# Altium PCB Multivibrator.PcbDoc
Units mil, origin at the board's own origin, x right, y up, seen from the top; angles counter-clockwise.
Board outline 2000 x 2000 mil, 2 copper layers (Top Layer, Bottom Layer); 9 components, 6 nets, 20 pads, 0 vias.
Unrouted connection lines stored in the file: 14.
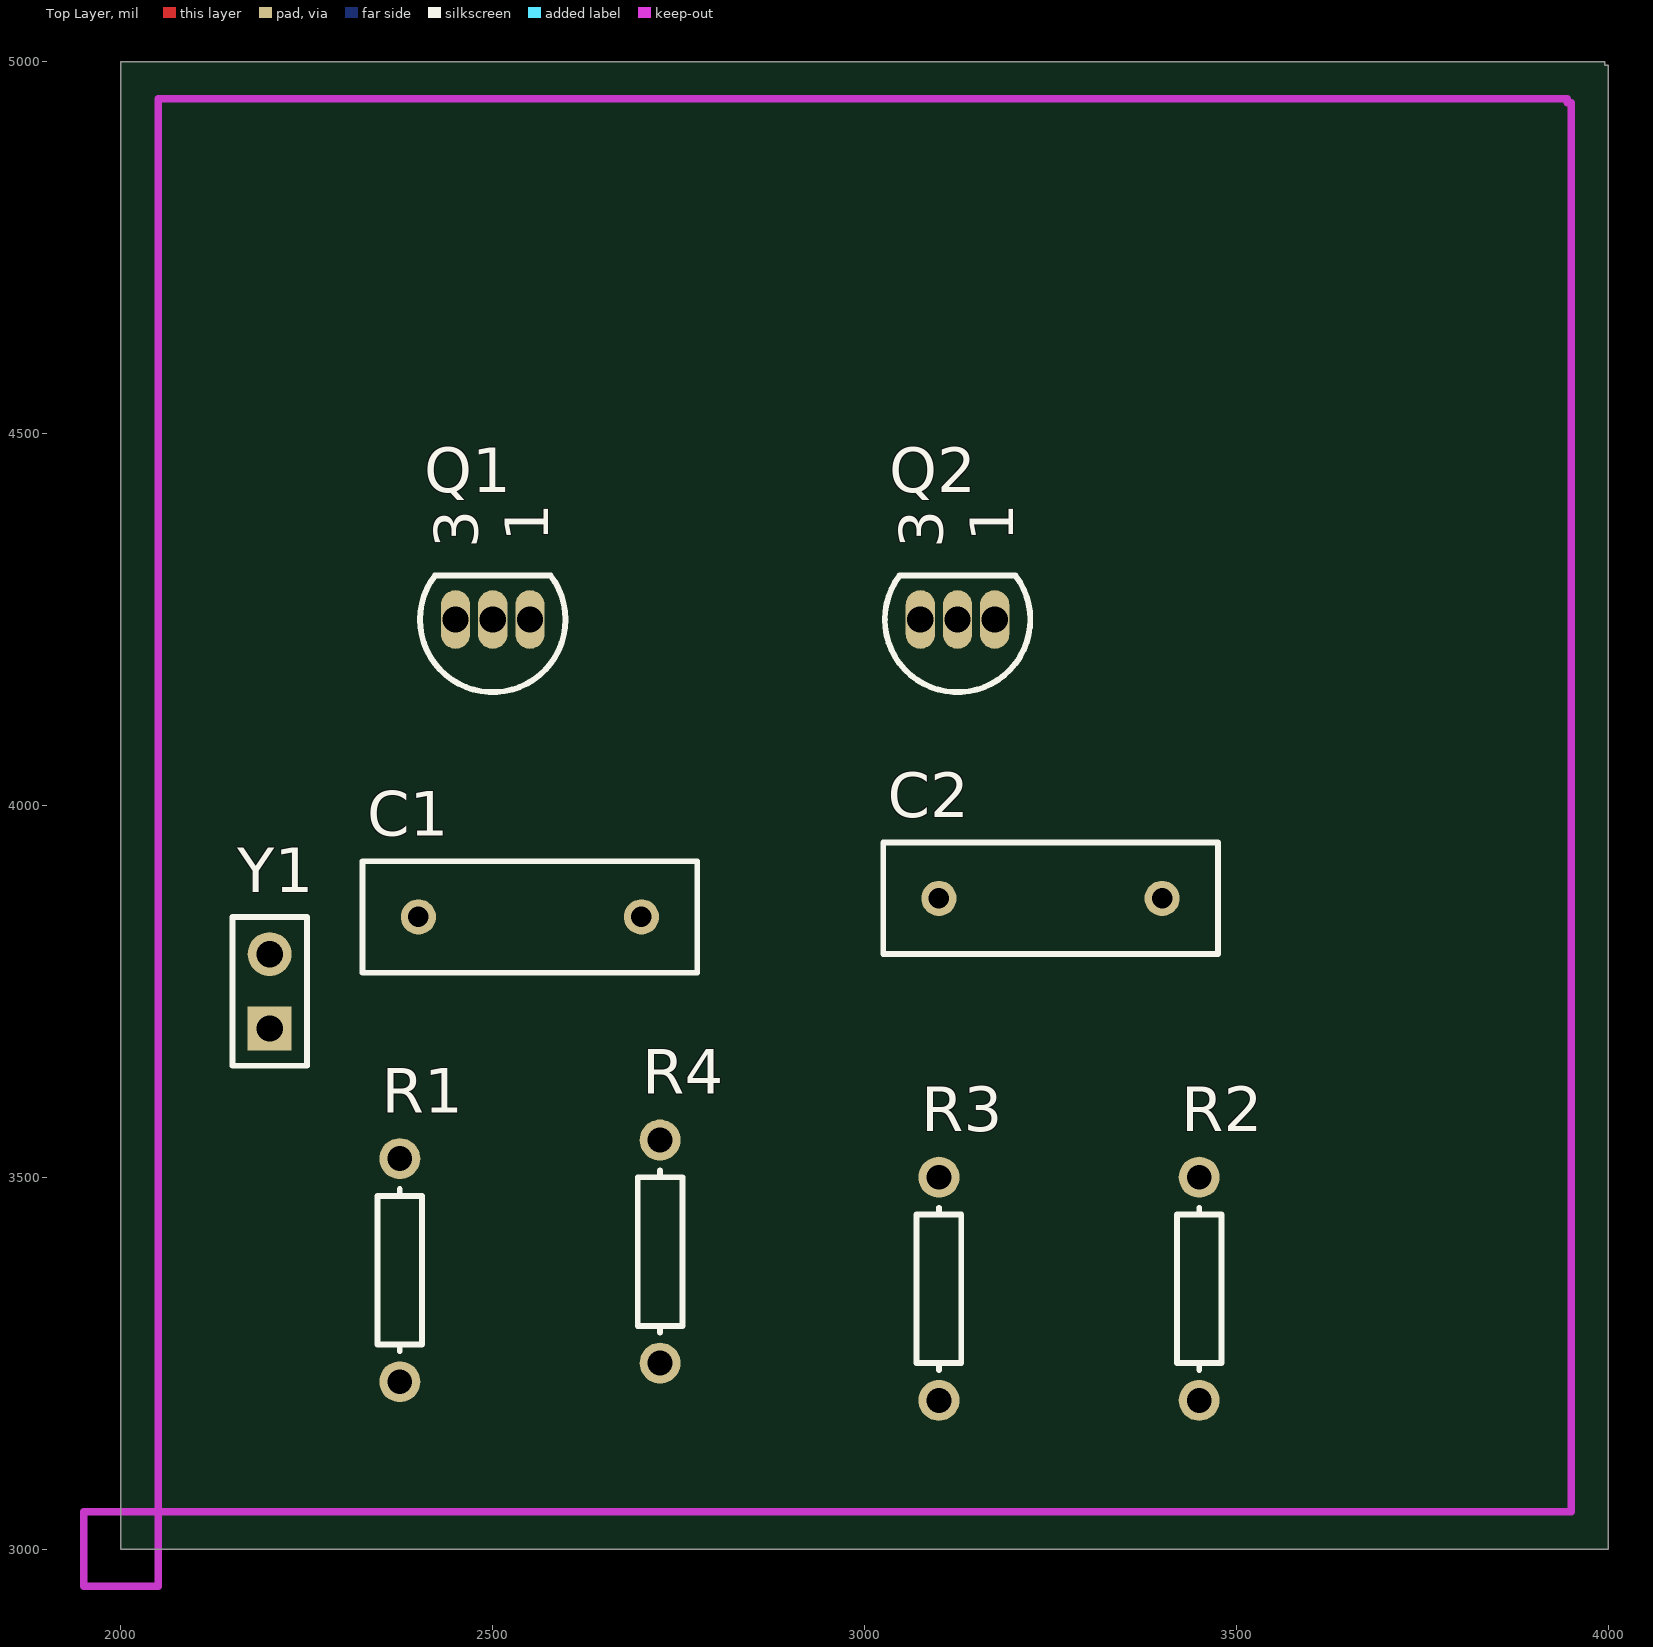
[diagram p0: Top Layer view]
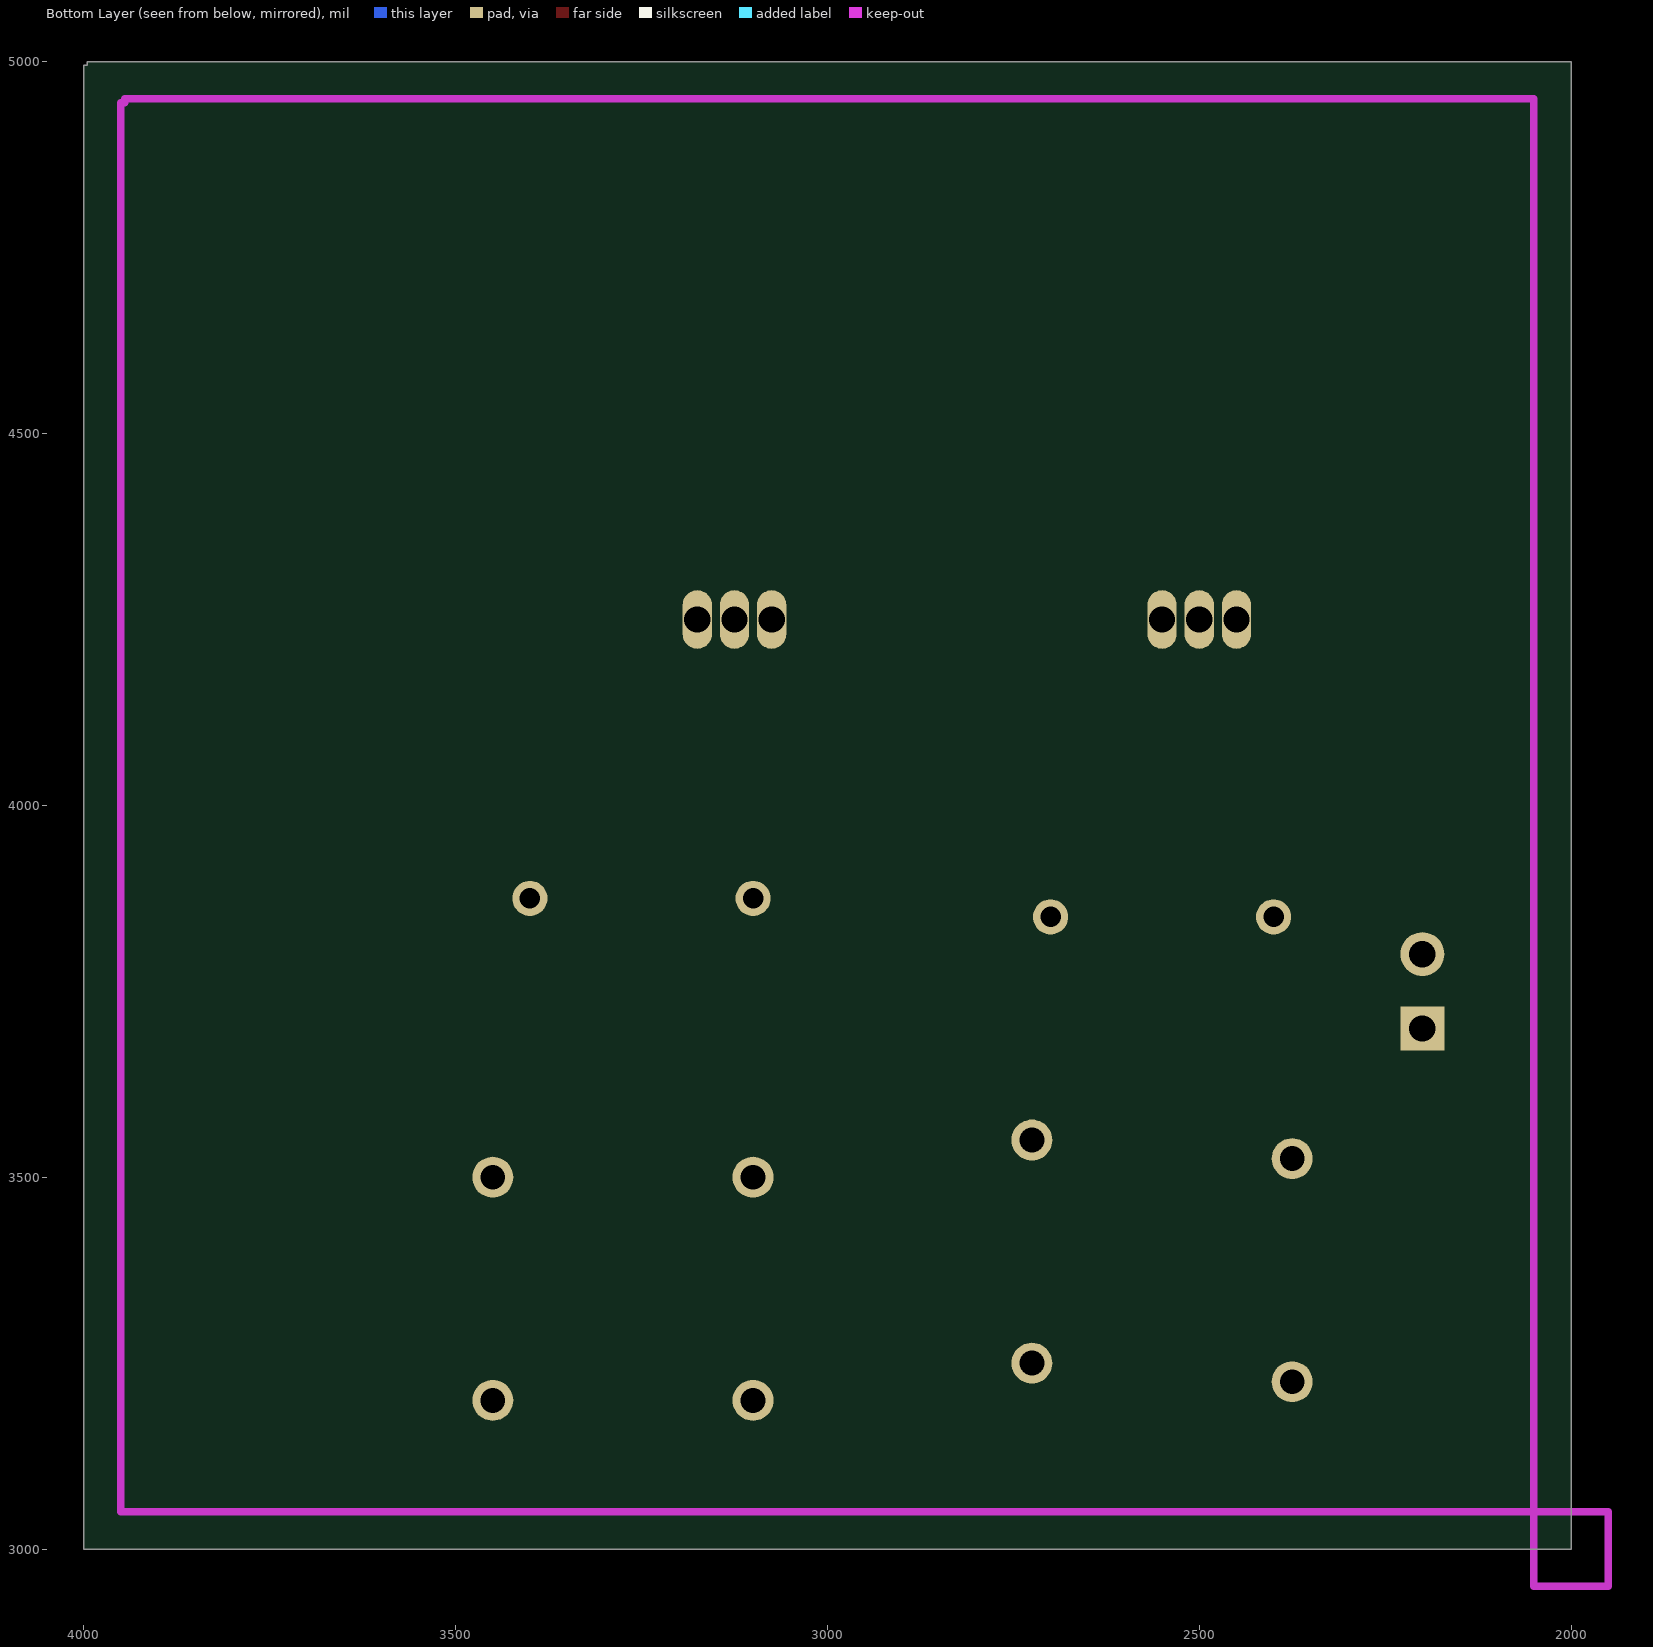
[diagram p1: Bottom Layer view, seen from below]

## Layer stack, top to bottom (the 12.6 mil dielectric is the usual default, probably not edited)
Top Layer: signal copper 1.4
Dielectric: core 12.6, FR-4, Dk 4.8
Bottom Layer: signal copper 1.4

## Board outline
2000,3000 4000,3000 4000,4995 3995,4995 3995,5000 2000,5000

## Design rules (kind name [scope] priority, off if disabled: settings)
Clearance [All] p1: gap=13
PolygonConnect [All] p1: connectstyle=Relief reliefconductorwidth=10 reliefentries=4 polygonreliefangle="90 Angle"
RoutingVias [All] p1: holewidth=32 width=62 viastyle="Through Hole" minholewidth=28 minwidth=50 maxholewidth=28 maxwidth=50
SilkscreenOverComponentPads [All] p1: minsilkscreentomaskgap=10
SolderMaskExpansion [All] p1: expansion=4
Width 12V [(InNet('12V') OR InNet('GND'))] p1: maxlimit=25 minlimit=25 preferedwidth=25
Width [All] p2: maxlimit=12 minlimit=12 preferedwidth=12
27 further rules are at their usual default settings.

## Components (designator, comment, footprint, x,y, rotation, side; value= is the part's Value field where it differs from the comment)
C1 "20n" RAD-0.3 2550,3850 r0 top
C2 "20n" RAD-0.3 3250,3875 r0 top
Q1 "2N3904" BCY-W3/E4 2500,4250 r90 top
Q2 "2N3904" BCY-W3/E4 3125,4250 r90 top
R1 "100k" AXIAL-0.3 2375,3375 r270 top
R2 "100k" AXIAL-0.3 3450,3350 r270 top
R3 "1k" AXIAL-0.3 3100,3350 r270 top
R4 "1k" AXIAL-0.3 2725,3400 r270 top
Y1 "Header 2" HDR1X2 2200,3700 r90 top

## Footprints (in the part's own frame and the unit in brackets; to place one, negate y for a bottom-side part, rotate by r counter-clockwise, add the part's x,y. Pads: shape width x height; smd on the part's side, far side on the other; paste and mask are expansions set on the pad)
AXIAL-0.3 [mm] "Axial Device, Thru-Hole; 2 Leads; 0.3 in Pin Spacing"
  round 1.4 hole 0.85: 1(-3.81,0) 2(3.81,0)
  silkscreen extent -2.77,-0.76 2.77,0.76
BCY-W3/E4 [mm] "TO, Flat Index; 3 In-Line, Axial Leads; Body Dia. 4.5mm; Leads 0.51 x 0.48 mm (max)"
  oval 2x1 hole 0.9: 1(0,-1.27) 2(0,0) 3(0,1.27)
  silkscreen extent -2.48,-2.48 1.5,2.48
HDR1X2 [mm] "Connector; Header; 2 Position"
  rect 1.5x1.5 hole 0.9: 1(0,0)
  round 1.5 hole 0.9: 2(2.54,0)
  silkscreen extent -1.27,-1.27 3.81,1.27
RAD-0.3 [mm] "Radial Cap, Thru-Hole; 2 Leads; 0.3 in Pin Spacing"
  round 1.2 hole 0.7: 1(-3.81,0) 2(3.81,0)
  silkscreen extent -5.71,-1.91 5.71,1.91

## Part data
C1 C2: library part Cap, "Capacitor"
Q1 Q2: "NPN General Purpose Amplifier"
R1 R2 R3 R4: library part Res1, "Resistor"
Y1: "Header, 2-Pin"

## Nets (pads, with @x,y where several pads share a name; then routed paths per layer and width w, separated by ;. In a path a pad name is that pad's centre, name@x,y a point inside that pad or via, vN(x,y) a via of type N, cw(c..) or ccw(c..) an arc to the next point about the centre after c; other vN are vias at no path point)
12V: R1.2 R2.2 R3.2 R4.2 Y1.1
GND: Q1.1 Q2.1 Y1.2
NetC1_1: C1.1 Q1.2 R1.1
NetC1_2: C1.2 Q2.3 R4.1
NetC2_1: C2.1 Q1.3 R3.1
NetC2_2: C2.2 Q2.2 R2.1

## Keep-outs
Keep-Out Layer:
  lines w10: 2050,3050 3950,3050 3950,4945 3945,4945 3945,4950 2050,4950 2050,3050 ; 2050,3050 2050,2950 1950,2950 1950,3050 2050,3050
